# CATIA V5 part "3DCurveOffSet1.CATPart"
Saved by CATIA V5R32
Part number: Part1
Bounding box of the stored display mesh (mm): x -47.659 to 151.901, y -137.348 to -39.765, z 0 to 40
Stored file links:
  D:\PROJECTS\Project 2022\CATIA V5 6R 2022\Resources\Part Files\c17_catia_v6_6r2022_prt\3DCurveOffSet1.CATPart
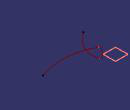
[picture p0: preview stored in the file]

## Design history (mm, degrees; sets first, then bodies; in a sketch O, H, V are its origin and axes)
Set1
  Sketch1 on xy-plane, origin (0, 0, 0), H (1, 0, 0), V (0, 1, 0)
    spline S1 through (-47.6585, -137.3483) (-29.3791, -10.2036) (-33.7949, 2.3216) (-29.4249, 29.9074)
  Plane1: type Offset, RefPlane xy-plane, Offset 20
  Sketch2 on Plane1, origin (0, 0, 20), H (1, 0, 0), V (0, 1, 0)
    spline S1 through (-28.771, 49.7054) (-11.6844, 72.6296) (11.4524, 88.4047) (30.8031, 89.9822) (65.2979, 82.489)
  Connect1: Curve1 Sketch1, Point1 vertex of Sketch1, Tension1 1, Curve2 Sketch2, Point2 vertex of Sketch2, Tension2 1
  Plane2: type Offset, RefPlane Plane1, Offset 20
  Sketch3 on Plane2, origin (0, 0, 40), H (1, 0, 0), V (0, 1, 0)
    spline S1 through (-172.8475, 33.6025) (-66.9858, 1.1425) (22.9569, -48.4801) (151.9012, -49.5994)
  Corner1 "Reference Curve": Element1 Sketch3, Element2 Connect1, Radius 10, Direction Plane2
Set2
  Point1: (0, 0, 0)
  Line1: type PtDir, RefPoint Point1, Direction xy-plane, Start 150, End 20
  Circle1: type CtrRad, Start 0, End 180, Center vertex of Line1, Support Plane2, Radius 80, FirstDirection (1, 0, 0)
Body1 (main body)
